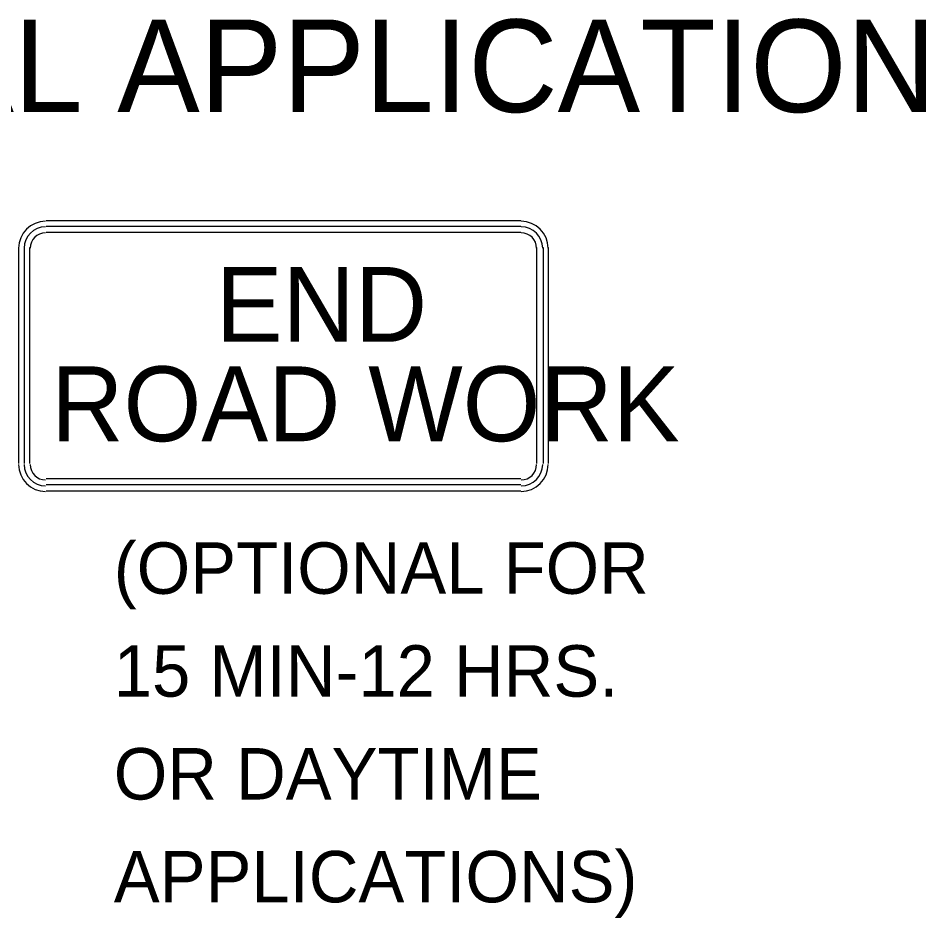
# Model space of a CAD drawing. Extents: x 15310.1 to 15319.5, y 15309 to 15319.1.
# Drawn here: x 15316.632 to 15317.691, y 15318.021 to 15319.071 of the extents above; entities that cross this region are included whole.
import ezdxf

# ---------------------------------------------------------------- set-up
doc = ezdxf.new("R2010")
doc.units = 0
for name, color, linetype in [('DETL-LINE', 7, 'Continuous'), ('DETL-NOTE', 7, 'Continuous'), ('DETL-TITL', 7, 'Continuous')]:
    doc.layers.add(name, color=color, linetype=linetype)

msp = doc.modelspace()

# ---------------------------------------------------------------- linework, layer by layer
at = {"layer": 'DETL-LINE'}
for p, q in [((15317.219, 15318.834), (15316.665, 15318.834)), ((15316.665, 15318.828), (15317.219, 15318.828)), ((15316.665, 15318.821), (15317.219, 15318.821)), ((15316.633, 15318.803), (15316.633, 15318.551)), ((15316.64, 15318.551), (15316.64, 15318.803)), ((15316.646, 15318.551), (15316.646, 15318.803)), ((15317.237, 15318.803), (15317.237, 15318.551)), ((15317.237, 15318.803), (15317.237, 15318.803)), ((15317.245, 15318.803), (15317.245, 15318.551)), ((15317.251, 15318.551), (15317.251, 15318.803)), ((15317.219, 15318.533), (15316.665, 15318.533)), ((15317.219, 15318.526), (15316.665, 15318.526)), ((15316.665, 15318.519), (15317.219, 15318.519))]:
    msp.add_line(p, q, dxfattribs=at)
for centre, radius, start, end in [((15316.6645, 15318.8021), 0.0316, 90, 180), ((15316.6645, 15318.8021), 0.0252, 90, 180), ((15317.2191, 15318.8021), 0.0316, 0, 90), ((15317.2191, 15318.8021), 0.0252, 0, 90), ((15316.6645, 15318.8021), 0.0181, 90, 180), ((15317.2191, 15318.8021), 0.0181, 0, 90), ((15316.6645, 15318.55), 0.0316, 180, 270), ((15316.6645, 15318.55), 0.0252, 180, 270), ((15316.6645, 15318.55), 0.0181, 180, 270), ((15317.2191, 15318.55), 0.0316, 270, 0), ((15317.2191, 15318.55), 0.0181, 270, 0), ((15317.2191, 15318.55), 0.0252, 270, 0)]:
    msp.add_arc(centre, radius, start, end, dxfattribs=at)

# ---------------------------------------------------------------- texts
for s, p in [('END', (15316.863, 15318.693)), ('ROAD WORK', (15316.671, 15318.577))]:
    msp.add_text(s, height=0.08731, rotation=360, dxfattribs=at).set_placement(p)
at = {"layer": 'DETL-NOTE'}
for s, p in [('(OPTIONAL FOR', (15316.744, 15318.399)), ('15 MIN-12 HRS. ', (15316.744, 15318.279)), ('OR DAYTIME', (15316.744, 15318.159)), ('APPLICATIONS)', (15316.744, 15318.039))]:
    msp.add_text(s, height=0.06, dxfattribs=at).set_placement(p)
at = {"layer": 'DETL-TITL'}
msp.add_text('TEMPORARY TRAFFIC CONTROL TYPICAL APPLICATION ', height=0.108, dxfattribs=at).set_placement((15313.755, 15318.961))

doc.saveas('drawing.dxf')
